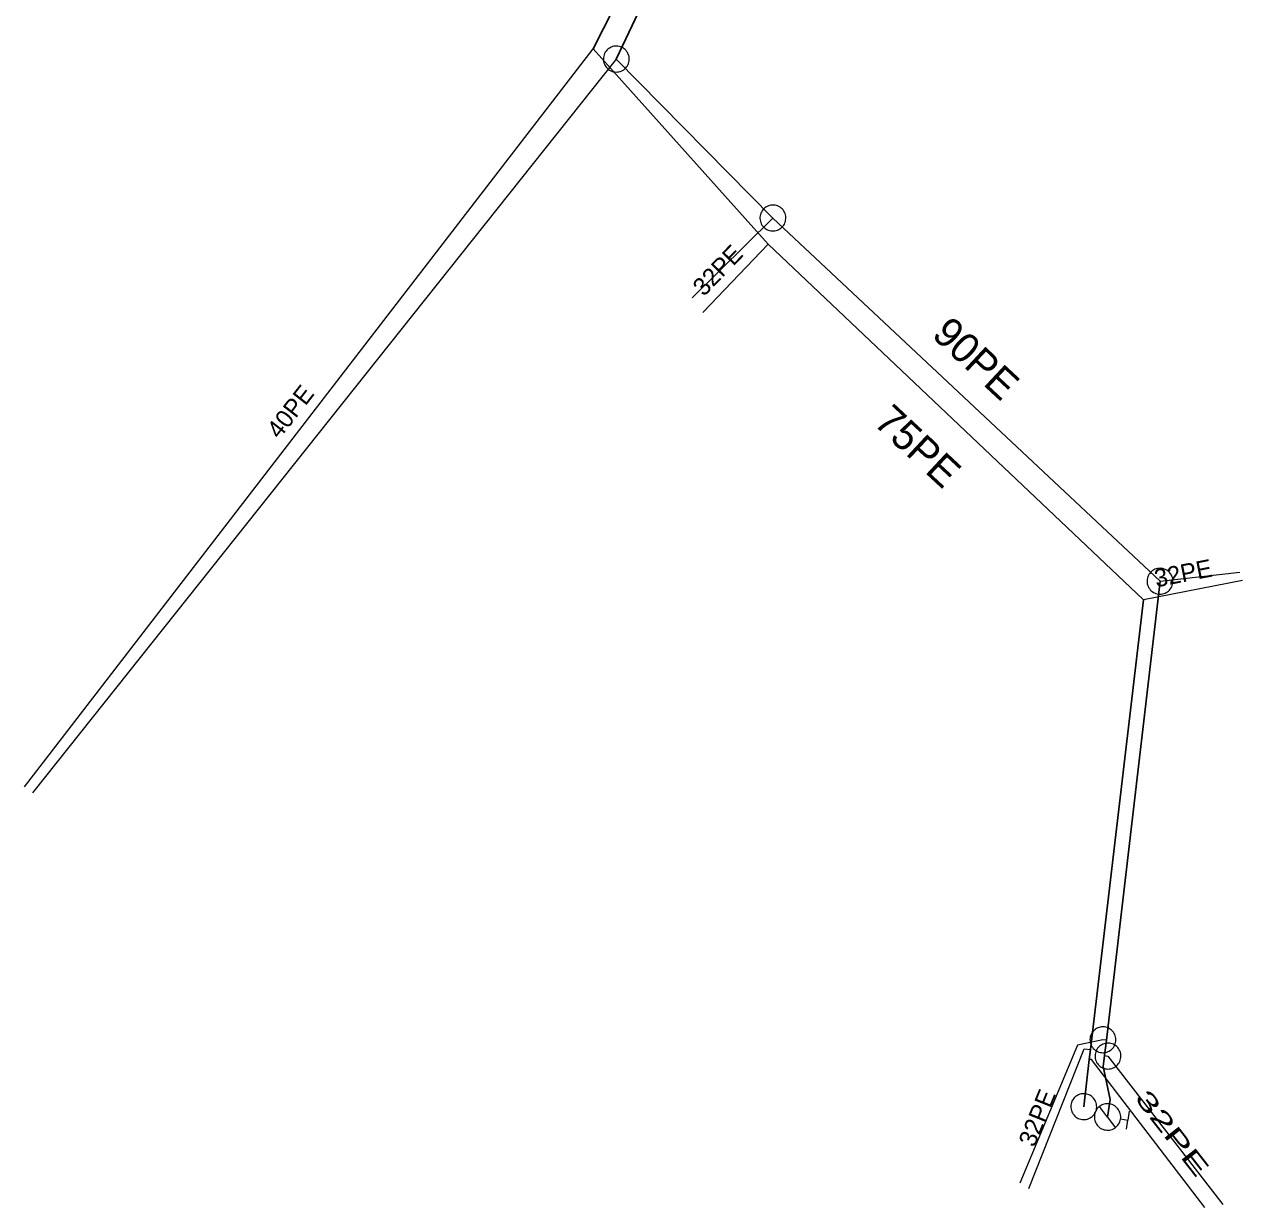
# Model space of a CAD drawing. Extents: x -741806 to -738704, y -1059275 to -1055387.
# Drawn here: x -740374.65 to -740333.49, y -1057702.02 to -1057662.05 of the extents above; entities that cross this region are included whole.
import ezdxf

# ---------------------------------------------------------------- set-up
doc = ezdxf.new("R2010")
doc.units = 0
doc.header["$LTSCALE"] = 0.4
for name, color, linetype, lineweight in [('2', 7, 'Continuous', 25), ('21', 7, 'Continuous', 13), ('3', 7, 'Continuous', 13), ('50', 7, 'Continuous', 13), ('51', 7, 'Continuous', 13), ('52', 7, 'Continuous', 25), ('56', 7, 'Continuous', 13)]:
    doc.layers.add(name, color=color, linetype=linetype, lineweight=lineweight)
for name, color, linetype in [('5', 7, 'Continuous'), ('53', 7, 'Continuous'), ('55', 7, 'Continuous')]:
    doc.layers.add(name, color=color, linetype=linetype)

msp = doc.modelspace()

# ---------------------------------------------------------------- linework, layer by layer
at = {"layer": '2'}
msp.add_lwpolyline([(-740338.859, -1057698.61), (-740338.671, -1057697.012), (-740338.633, -1057696.683), (-740336.84, -1057681.49), (-740349.52, -1057669.47), (-740355.43, -1057662.87), (-740352.309, -1057656.73), (-740347.611, -1057650.21), (-740346.649, -1057636.22)], dxfattribs=at)
at = {"layer": '21'}
for p, q in [((-740354.649, -1057663.22), (-740374.37, -1057688.01)), ((-740349.359, -1057668.59), (-740352.09, -1057671.28)), ((-740336.28, -1057680.86), (-740333.579, -1057680.55))]:
    msp.add_line(p, q, dxfattribs=at)
for points in [[(-740338.094, -1057696.362), (-740338.21, -1057696.35), (-740339.067, -1057696.529), (-740341.02, -1057701.19)], [(-740338.156, -1057696.886), (-740338.039, -1057696.899), (-740334.16, -1057701.909)]]:
    msp.add_lwpolyline(points, dxfattribs=at)
at = {"layer": '3'}
msp.add_lwpolyline([(-740338.807, -1057698.175), (-740338.852, -1057698.172), (-740338.897, -1057698.174), (-740338.943, -1057698.181), (-740338.987, -1057698.192), (-740339.03, -1057698.208), (-740339.072, -1057698.228), (-740339.11, -1057698.253), (-740339.146, -1057698.28), (-740339.178, -1057698.313), (-740339.208, -1057698.348), (-740339.233, -1057698.386), (-740339.255, -1057698.427), (-740339.271, -1057698.469), (-740339.285, -1057698.513), (-740339.292, -1057698.558), (-740339.295, -1057698.604), (-740339.293, -1057698.65), (-740339.287, -1057698.695), (-740339.275, -1057698.739), (-740339.259, -1057698.783), (-740339.239, -1057698.823), (-740339.215, -1057698.861), (-740339.186, -1057698.898), (-740339.155, -1057698.931), (-740339.119, -1057698.96), (-740339.081, -1057698.985), (-740339.041, -1057699.007), (-740338.998, -1057699.024), (-740338.954, -1057699.036), (-740338.908, -1057699.044), (-740338.863, -1057699.047), (-740338.818, -1057699.045), (-740338.772, -1057699.039), (-740338.727, -1057699.027), (-740338.685, -1057699.012), (-740338.643, -1057698.991), (-740338.605, -1057698.967), (-740338.569, -1057698.938), (-740338.537, -1057698.906), (-740338.507, -1057698.872), (-740338.482, -1057698.833), (-740338.46, -1057698.793), (-740338.443, -1057698.75), (-740338.43, -1057698.706), (-740338.423, -1057698.661), (-740338.42, -1057698.615), (-740338.421, -1057698.57), (-740338.428, -1057698.524), (-740338.44, -1057698.48), (-740338.456, -1057698.437), (-740338.476, -1057698.396), (-740338.5, -1057698.357), (-740338.529, -1057698.321), (-740338.56, -1057698.288), (-740338.596, -1057698.259), (-740338.634, -1057698.233), (-740338.674, -1057698.212), (-740338.717, -1057698.195), (-740338.761, -1057698.183), (-740338.806, -1057698.175)], dxfattribs=at)
at = {"layer": '50'}
for p, q in [((-740338.054, -1057698.959), (-740338.32, -1057698.598)), ((-740337.317, -1057698.759), (-740337.364, -1057699.063)), ((-740338.054, -1057698.959), (-740337.793, -1057699.317)), ((-740337.612, -1057699.025), (-740337.364, -1057699.063)), ((-740337.41, -1057699.367), (-740337.364, -1057699.063))]:
    msp.add_line(p, q, dxfattribs=at)
msp.add_lwpolyline([(-740338.125, -1057699.397), (-740338.076, -1057699.402), (-740338.03, -1057699.404), (-740337.982, -1057699.398), (-740337.937, -1057699.387), (-740337.895, -1057699.375), (-740337.85, -1057699.354), (-740337.811, -1057699.331), (-740337.772, -1057699.303), (-740337.737, -1057699.273), (-740337.707, -1057699.237), (-740337.679, -1057699.2), (-740337.654, -1057699.16), (-740337.637, -1057699.117), (-740337.622, -1057699.072), (-740337.612, -1057699.027), (-740337.608, -1057698.981), (-740337.606, -1057698.936), (-740337.612, -1057698.889), (-740337.622, -1057698.843), (-740337.637, -1057698.797), (-740337.656, -1057698.756), (-740337.679, -1057698.715), (-740337.706, -1057698.677), (-740337.737, -1057698.643), (-740337.772, -1057698.61), (-740337.809, -1057698.582), (-740337.849, -1057698.56), (-740337.893, -1057698.539), (-740337.938, -1057698.527), (-740337.982, -1057698.515), (-740338.03, -1057698.51), (-740338.077, -1057698.511), (-740338.121, -1057698.516), (-740338.169, -1057698.525), (-740338.213, -1057698.54), (-740338.256, -1057698.558), (-740338.295, -1057698.582), (-740338.334, -1057698.609), (-740338.37, -1057698.642), (-740338.399, -1057698.676), (-740338.427, -1057698.715), (-740338.45, -1057698.755), (-740338.47, -1057698.795), (-740338.485, -1057698.842), (-740338.495, -1057698.887), (-740338.499, -1057698.933), (-740338.498, -1057698.98), (-740338.494, -1057699.027), (-740338.485, -1057699.072), (-740338.47, -1057699.118), (-740338.452, -1057699.159), (-740338.428, -1057699.201), (-740338.401, -1057699.238), (-740338.371, -1057699.273), (-740338.334, -1057699.303), (-740338.298, -1057699.332), (-740338.257, -1057699.356), (-740338.214, -1057699.372), (-740338.17, -1057699.387)], close=True, dxfattribs=at)
at = {"layer": '51'}
for points in [[(-740354.836, -1057663.614), (-740354.794, -1057663.632), (-740354.751, -1057663.645), (-740354.705, -1057663.653), (-740354.66, -1057663.657), (-740354.614, -1057663.655), (-740354.568, -1057663.649), (-740354.524, -1057663.638), (-740354.481, -1057663.623), (-740354.44, -1057663.603), (-740354.401, -1057663.579), (-740354.364, -1057663.551), (-740354.331, -1057663.519), (-740354.301, -1057663.485), (-740354.275, -1057663.447), (-740354.254, -1057663.406), (-740354.236, -1057663.364), (-740354.223, -1057663.32), (-740354.215, -1057663.275), (-740354.212, -1057663.229), (-740354.214, -1057663.183), (-740354.22, -1057663.138), (-740354.23, -1057663.093), (-740354.246, -1057663.05), (-740354.265, -1057663.009), (-740354.29, -1057662.97), (-740354.318, -1057662.933), (-740354.349, -1057662.901), (-740354.385, -1057662.871), (-740354.422, -1057662.845), (-740354.462, -1057662.823), (-740354.504, -1057662.806), (-740354.548, -1057662.793), (-740354.594, -1057662.785), (-740354.639, -1057662.782), (-740354.685, -1057662.783), (-740354.731, -1057662.789), (-740354.775, -1057662.8), (-740354.818, -1057662.815), (-740354.859, -1057662.836), (-740354.898, -1057662.859), (-740354.934, -1057662.887), (-740354.968, -1057662.919), (-740354.997, -1057662.954), (-740355.023, -1057662.991), (-740355.045, -1057663.032), (-740355.063, -1057663.074), (-740355.075, -1057663.118), (-740355.084, -1057663.163), (-740355.087, -1057663.209), (-740355.085, -1057663.255), (-740355.079, -1057663.3), (-740355.069, -1057663.345), (-740355.053, -1057663.388), (-740355.034, -1057663.429), (-740355.009, -1057663.468), (-740354.981, -1057663.505), (-740354.95, -1057663.537), (-740354.914, -1057663.567), (-740354.877, -1057663.593), (-740354.837, -1057663.614)], [(-740349.67, -1057668.896), (-740349.637, -1057668.927), (-740349.601, -1057668.954), (-740349.56, -1057668.977), (-740349.52, -1057668.996), (-740349.476, -1057669.01), (-740349.431, -1057669.021), (-740349.385, -1057669.025), (-740349.339, -1057669.026), (-740349.294, -1057669.021), (-740349.25, -1057669.012), (-740349.206, -1057668.998), (-740349.163, -1057668.98), (-740349.123, -1057668.958), (-740349.086, -1057668.931), (-740349.052, -1057668.9), (-740349.021, -1057668.867), (-740348.994, -1057668.83), (-740348.971, -1057668.791), (-740348.952, -1057668.748), (-740348.938, -1057668.705), (-740348.928, -1057668.66), (-740348.922, -1057668.615), (-740348.922, -1057668.569), (-740348.926, -1057668.524), (-740348.936, -1057668.478), (-740348.95, -1057668.434), (-740348.968, -1057668.393), (-740348.991, -1057668.353), (-740349.017, -1057668.316), (-740349.048, -1057668.281), (-740349.081, -1057668.251), (-740349.118, -1057668.224), (-740349.158, -1057668.2), (-740349.199, -1057668.182), (-740349.243, -1057668.167), (-740349.288, -1057668.157), (-740349.333, -1057668.152), (-740349.379, -1057668.151), (-740349.424, -1057668.157), (-740349.469, -1057668.165), (-740349.513, -1057668.179), (-740349.555, -1057668.197), (-740349.594, -1057668.22), (-740349.632, -1057668.246), (-740349.666, -1057668.277), (-740349.698, -1057668.311), (-740349.724, -1057668.348), (-740349.748, -1057668.387), (-740349.766, -1057668.429), (-740349.781, -1057668.473), (-740349.79, -1057668.517), (-740349.796, -1057668.563), (-740349.796, -1057668.609), (-740349.792, -1057668.654), (-740349.783, -1057668.699), (-740349.769, -1057668.743), (-740349.751, -1057668.784), (-740349.728, -1057668.825), (-740349.701, -1057668.862), (-740349.671, -1057668.895)], [(-740335.961, -1057681.159), (-740335.932, -1057681.125), (-740335.906, -1057681.087), (-740335.884, -1057681.046), (-740335.867, -1057681.004), (-740335.854, -1057680.96), (-740335.846, -1057680.915), (-740335.843, -1057680.869), (-740335.844, -1057680.823), (-740335.851, -1057680.778), (-740335.862, -1057680.734), (-740335.877, -1057680.691), (-740335.897, -1057680.649), (-740335.921, -1057680.61), (-740335.949, -1057680.574), (-740335.981, -1057680.541), (-740336.016, -1057680.511), (-740336.053, -1057680.485), (-740336.094, -1057680.464), (-740336.137, -1057680.447), (-740336.181, -1057680.434), (-740336.226, -1057680.427), (-740336.271, -1057680.422), (-740336.317, -1057680.425), (-740336.362, -1057680.43), (-740336.407, -1057680.442), (-740336.45, -1057680.457), (-740336.491, -1057680.477), (-740336.53, -1057680.501), (-740336.566, -1057680.529), (-740336.6, -1057680.561), (-740336.629, -1057680.596), (-740336.654, -1057680.633), (-740336.676, -1057680.674), (-740336.693, -1057680.716), (-740336.706, -1057680.76), (-740336.715, -1057680.806), (-740336.717, -1057680.851), (-740336.717, -1057680.897), (-740336.709, -1057680.942), (-740336.699, -1057680.986), (-740336.683, -1057681.03), (-740336.664, -1057681.072), (-740336.639, -1057681.11), (-740336.612, -1057681.146), (-740336.58, -1057681.179), (-740336.545, -1057681.209), (-740336.506, -1057681.234), (-740336.467, -1057681.256), (-740336.424, -1057681.273), (-740336.379, -1057681.286), (-740336.335, -1057681.294), (-740336.289, -1057681.298), (-740336.243, -1057681.296), (-740336.198, -1057681.29), (-740336.153, -1057681.279), (-740336.11, -1057681.263), (-740336.069, -1057681.244), (-740336.03, -1057681.219), (-740335.994, -1057681.191), (-740335.962, -1057681.16)], [(-740338.644, -1057696.3), (-740338.647, -1057696.345), (-740338.645, -1057696.39), (-740338.638, -1057696.436), (-740338.627, -1057696.48), (-740338.611, -1057696.523), (-740338.59, -1057696.565), (-740338.565, -1057696.603), (-740338.537, -1057696.639), (-740338.504, -1057696.671), (-740338.47, -1057696.7), (-740338.431, -1057696.725), (-740338.39, -1057696.747), (-740338.348, -1057696.764), (-740338.304, -1057696.776), (-740338.259, -1057696.783), (-740338.213, -1057696.786), (-740338.167, -1057696.785), (-740338.122, -1057696.778), (-740338.077, -1057696.765), (-740338.034, -1057696.749), (-740337.994, -1057696.729), (-740337.955, -1057696.705), (-740337.919, -1057696.676), (-740337.887, -1057696.644), (-740337.857, -1057696.608), (-740337.832, -1057696.57), (-740337.811, -1057696.53), (-740337.794, -1057696.487), (-740337.782, -1057696.443), (-740337.774, -1057696.397), (-740337.772, -1057696.352), (-740337.774, -1057696.307), (-740337.781, -1057696.261), (-740337.792, -1057696.217), (-740337.808, -1057696.174), (-740337.829, -1057696.132), (-740337.854, -1057696.094), (-740337.882, -1057696.058), (-740337.914, -1057696.026), (-740337.949, -1057695.997), (-740337.988, -1057695.972), (-740338.028, -1057695.95), (-740338.071, -1057695.934), (-740338.115, -1057695.921), (-740338.16, -1057695.914), (-740338.206, -1057695.911), (-740338.252, -1057695.913), (-740338.297, -1057695.919), (-740338.341, -1057695.932), (-740338.384, -1057695.948), (-740338.425, -1057695.968), (-740338.464, -1057695.992), (-740338.499, -1057696.021), (-740338.532, -1057696.053), (-740338.561, -1057696.089), (-740338.587, -1057696.127), (-740338.608, -1057696.167), (-740338.625, -1057696.211), (-740338.637, -1057696.254), (-740338.644, -1057696.299)], [(-740337.605, -1057696.951), (-740337.601, -1057696.906), (-740337.603, -1057696.861), (-740337.609, -1057696.815), (-740337.62, -1057696.771), (-740337.636, -1057696.728), (-740337.656, -1057696.686), (-740337.681, -1057696.648), (-740337.709, -1057696.611), (-740337.741, -1057696.579), (-740337.776, -1057696.55), (-740337.814, -1057696.524), (-740337.855, -1057696.502), (-740337.897, -1057696.485), (-740337.941, -1057696.473), (-740337.986, -1057696.465), (-740338.032, -1057696.462), (-740338.078, -1057696.463), (-740338.123, -1057696.47), (-740338.167, -1057696.482), (-740338.211, -1057696.497), (-740338.251, -1057696.518), (-740338.291, -1057696.541), (-740338.326, -1057696.57), (-740338.359, -1057696.601), (-740338.389, -1057696.637), (-740338.414, -1057696.675), (-740338.435, -1057696.715), (-740338.453, -1057696.758), (-740338.465, -1057696.802), (-740338.474, -1057696.848), (-740338.476, -1057696.893), (-740338.474, -1057696.938), (-740338.468, -1057696.984), (-740338.457, -1057697.028), (-740338.441, -1057697.071), (-740338.421, -1057697.113), (-740338.396, -1057697.151), (-740338.369, -1057697.188), (-740338.336, -1057697.22), (-740338.301, -1057697.249), (-740338.263, -1057697.275), (-740338.223, -1057697.297), (-740338.18, -1057697.313), (-740338.136, -1057697.326), (-740338.091, -1057697.334), (-740338.045, -1057697.337), (-740337.999, -1057697.335), (-740337.954, -1057697.329), (-740337.91, -1057697.317), (-740337.867, -1057697.302), (-740337.826, -1057697.281), (-740337.787, -1057697.258), (-740337.751, -1057697.229), (-740337.718, -1057697.198), (-740337.689, -1057697.162), (-740337.663, -1057697.124), (-740337.642, -1057697.084), (-740337.625, -1057697.041), (-740337.612, -1057696.997), (-740337.605, -1057696.952)]]:
    msp.add_lwpolyline(points, dxfattribs=at)
at = {"layer": '52'}
msp.add_lwpolyline([(-740349.517, -1057633.908), (-740347.05, -1057650.55), (-740351.55, -1057656.669), (-740354.649, -1057663.22), (-740349.359, -1057668.59), (-740336.28, -1057680.86), (-740338.094, -1057696.362), (-740338.156, -1057696.886), (-740338.199, -1057697.254), (-740337.96, -1057698.37), (-740338.05, -1057698.96)], dxfattribs=at)
at = {"layer": '56'}
for p, q in [((-740374.649, -1057687.8), (-740355.43, -1057662.87)), ((-740351.73, -1057671.78), (-740349.52, -1057669.47)), ((-740333.489, -1057680.83), (-740336.84, -1057681.49))]:
    msp.add_line(p, q, dxfattribs=at)
for points in [[(-740340.71, -1057701.37), (-740338.84, -1057696.659), (-740338.633, -1057696.683)], [(-740334.77, -1057702.02), (-740338.6, -1057697.02), (-740338.671, -1057697.012)]]:
    msp.add_lwpolyline(points, dxfattribs=at)

# ---------------------------------------------------------------- texts
at = {"layer": '5'}
msp.add_text('75PE', height=1, rotation=317, dxfattribs=at).set_placement((-740345.996, -1057675.543))
at = {"layer": '53'}
msp.add_text('90PE', height=1, rotation=317, dxfattribs=at).set_placement((-740344.029, -1057672.581))
at = {"layer": '55'}
for s, rotation, p in [('32PE', 46, (-740351.692, -1057671.263)), ('40PE', 52, (-740366.034, -1057676.082)), ('32PE', 11, (-740336.405, -1057681.067)), ('32PE', 68, (-740340.524, -1057700.008))]:
    msp.add_text(s, height=0.6, rotation=rotation, dxfattribs=at).set_placement(p)
at = {"layer": '55', "width": 1.75}
msp.add_text('32PE', height=0.6, rotation=308, dxfattribs=at).set_placement((-740337.156, -1057698.334))

doc.saveas('drawing.dxf')
